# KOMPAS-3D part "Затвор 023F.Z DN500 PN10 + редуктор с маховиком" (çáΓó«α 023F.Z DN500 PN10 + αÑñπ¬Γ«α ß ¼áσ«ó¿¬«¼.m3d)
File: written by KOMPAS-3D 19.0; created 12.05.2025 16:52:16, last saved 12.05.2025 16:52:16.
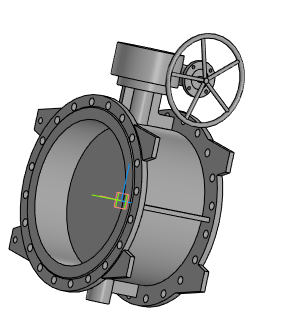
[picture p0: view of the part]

Document properties: Полное имя файла: Затвор 023F.Z DN500 PN10 + редуктор с маховиком.a3d

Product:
- Part/product: Затвор 023F.Z DN500 PN10 + редуктор с маховиком
    Масса: 260.14

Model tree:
1. Операция без истории:1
